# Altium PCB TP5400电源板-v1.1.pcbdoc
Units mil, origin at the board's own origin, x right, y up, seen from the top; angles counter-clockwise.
Board outline 629.92 x 807.09 mil, 2 copper layers (Top Layer, Bottom Layer), stack 62.205 mil thick; 18 components, 11 nets, 48 pads, 36 vias.
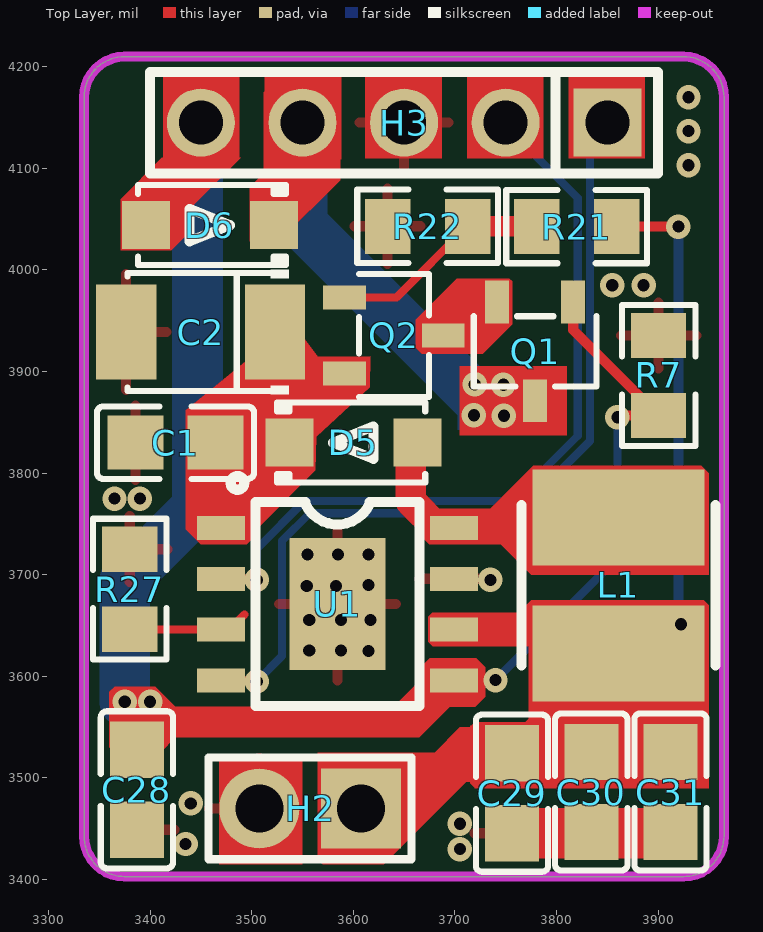
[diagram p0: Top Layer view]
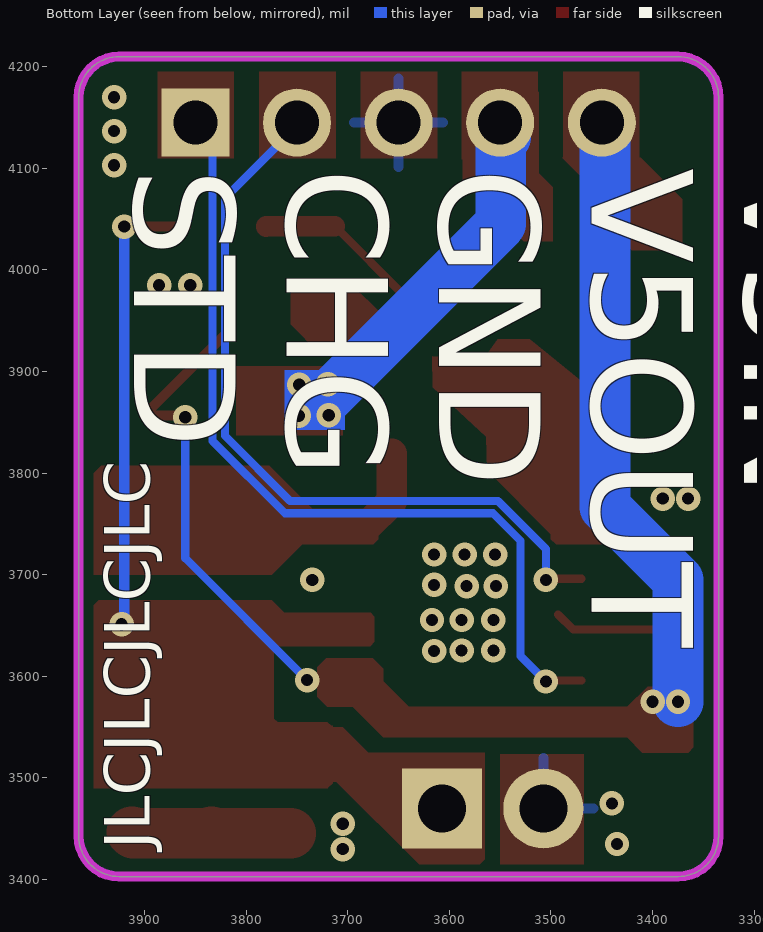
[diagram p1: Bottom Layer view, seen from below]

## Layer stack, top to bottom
Top Solder Mask Layer: solder mask 0.394, Dk 3.3
Top Layer: signal copper 1.378
Dielectric2: surface 59.449, FR4, Dk 4.5
Bottom Layer: signal copper 1.378
Bottom Solder Mask Layer: solder mask 0.394, Dk 3.3

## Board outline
3375,4210 3924.92,4210 cw(c3924.92,4170) 3964.92,4170 3964.92,3442.91 cw(c3924.92,3442.91) 3924.92,3402.91 3375,3402.91 cw(c3375,3442.91) 3335,3442.91 3335,4170 cw(c3375,4170)

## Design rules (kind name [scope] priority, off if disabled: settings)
BoardOutlineClearance copperThickness1oz [All] p0: genericclearance=10 ignorepadtopadclearanceinfootprint=FALSE except(0: Arc-SplitContinuation Track-SplitContinuation SMDPad-SplitContinuation THPad-SplitContinuation Via-SplitContinuation Fill-SplitContinuation Poly-SplitContinuation Region-SplitContinuation Text-SplitContinuation)
BoardOutlineClearance copperThickness2oz [All] p0: genericclearance=10 ignorepadtopadclearanceinfootprint=FALSE except(0: Arc-SplitContinuation Track-SplitContinuation SMDPad-SplitContinuation THPad-SplitContinuation Via-SplitContinuation Fill-SplitContinuation Poly-SplitContinuation Region-SplitContinuation Text-SplitContinuation)
BoardOutlineClearance Plane_innerPlane [All] p0: genericclearance=10 ignorepadtopadclearanceinfootprint=FALSE except(0: Arc-SplitContinuation Track-SplitContinuation SMDPad-SplitContinuation THPad-SplitContinuation Via-SplitContinuation Fill-SplitContinuation Poly-SplitContinuation Region-SplitContinuation Text-SplitContinuation)
BoardOutlineClearance Copper_copperRegion [All] p0: genericclearance=10 ignorepadtopadclearanceinfootprint=FALSE except(0: Arc-SplitContinuation Track-SplitContinuation SMDPad-SplitContinuation THPad-SplitContinuation Via-SplitContinuation Fill-SplitContinuation Poly-SplitContinuation Region-SplitContinuation Text-SplitContinuation)
BoardOutlineClearance otherClearance [All] p0: genericclearance=10 ignorepadtopadclearanceinfootprint=FALSE except(0: Arc-SplitContinuation Track-SplitContinuation SMDPad-SplitContinuation THPad-SplitContinuation Via-SplitContinuation Fill-SplitContinuation Poly-SplitContinuation Region-SplitContinuation Text-SplitContinuation)
Clearance copperThickness1oz [All] p1: gap=7 ignorepadtopadclearanceinfootprint=FALSE
Clearance copperThickness2oz [All] p1: gap=7 ignorepadtopadclearanceinfootprint=FALSE
Clearance Plane_innerPlane [All] p1: gap=7 ignorepadtopadclearanceinfootprint=FALSE
Clearance Copper_copperRegion [All] p1: gap=7 ignorepadtopadclearanceinfootprint=FALSE
Clearance otherClearance [All] p1: gap=7 ignorepadtopadclearanceinfootprint=FALSE
DiffPairsRouting differentialPair [All] p1: maxuncoupledlength=10 minlimit=6 maxlimit=Infinity mostfreqgap=6 toplayer_minwidth=5 toplayer_prefwidth=10 toplayer_maxwidth=100 bottomlayer_minwidth=5 bottomlayer_prefwidth=10 bottomlayer_maxwidth=100
PasteMaskExpansion pasteMaskExpansion [All] p1: expansion=0
PlaneConnect innerPlane [All] p1: planeconnectstyle=Relief reliefexpansion=20 reliefentries=4 reliefconductorwidth=10 reliefairgap=10
PolygonConnect copperRegion [All] p1: connectstyle=Relief reliefentries=4 reliefconductorwidth=10 polygonreliefangle="90 Angle" airgapwidth=10
RoutingVias viaSize [All] p1: viastyle="Through Hole" holewidth=12.0078 minholewidth=11.811 maxholewidth=248.0314 width=12.0078 minwidth=11.811 maxwidth=248.0314
SolderMaskExpansion solderMaskExpansion [All] p1: useseparateexpansions=TRUE expansion=2 expansionbottom=2
Width copperThickness1oz [All] p1: maxlimit=100 minlimit=5 preferedwidth=10
Width copperThickness2oz [All] p1: maxlimit=100 minlimit=8 preferedwidth=10

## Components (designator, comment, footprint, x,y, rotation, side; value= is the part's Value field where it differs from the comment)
C1 "" C0805_1 3425,3830 r0 top
C2 "" CASE-B_3528 3449.7,3938.89 r180 top
C28 "" C0805_1 3387.05,3488.37 r270 top
C29 "" C0805_1 3756.26,3485 r90 top
C30 "" C0805_1 3834.25,3486.18 r90 top
C31 "" C0805_1 3912.26,3486.18 r90 top
D5 "" SOD-123FL_L2.8-W1.8-LS3.7-RD 3600,3830 r0 top
D6 "" SOD-123FL_L2.8-W1.8-LS3.7-RD 3458.78,4044.08 r180 top
H2 "" HDR-TH_2P-P2.54-V-M_1 3557.48,3470 r180 top
H3 "" HDR-TH_5P-P2.54-V-M_1 3650,4145 r180 top
L1 "" IND-SMD_L4.5-W4.0_SCCD43 3861.04,3689.67 r270 top
Q1 "" SOT-23-3_L2.9-W1.6-P1.90-LS2.8-BR_1 3779.04,3920 r90 top
Q2 "" SOT-23-3_L2.9-W1.6-P1.90-LS2.8-BR_1 3640,3935.58 r180 top
R7 "" R0805_1 3900.57,3896.21 r270 top
R21 "" R0805_1 3819.88,4042.7 r180 top
R22 "" R0805_1 3673.23,4042.99 r180 top
R27 "" R0805_1 3380,3685.82 r270 top
U1 "" ESOP-8_L4.9-W3.9-P1.27-LS6.0-BL-EP 3584.43,3671.09 r270 top

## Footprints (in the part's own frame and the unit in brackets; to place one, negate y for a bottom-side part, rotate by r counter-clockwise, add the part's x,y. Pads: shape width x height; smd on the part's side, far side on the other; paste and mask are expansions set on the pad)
C0805_1 [mm]
  rect 1.41x1.35 smd: 1(-1,0) 2(1,0)
  silkscreen extent -1.96,-0.9 1.96,0.9
CASE-B_3528 [mil]
  rect 59.3x93.54 smd: 1(-73.25,0) 2(73.25,0)
  silkscreen extent -87,-61 72,61
ESOP-8_L4.9-W3.9-P1.27-LS6.0-BL-EP [mm]
  rect 0.6x1.2 smd: 1(-1.905,-2.908) 2(-0.635,-2.908) 3(0.635,-2.908) 4(1.905,-2.908) 5(1.905,2.908) 6(0.635,2.908) 7(-0.635,2.908) 8(-1.905,2.908)
  rect 3.3x2.4 smd: 9(0,0)
  silkscreen extent -3.2,-2.67 2.55,2.05
HDR-TH_2P-P2.54-V-M_1 [mm]
  rect 2x2 hole 1.2: 1(-1.27,0)
  round 2 hole 1.2: 2(1.27,0)
  silkscreen extent -2.54,-1.27 2.54,1.27
HDR-TH_5P-P2.54-V-M_1 [mm]
  rect 1.7x1.7 hole 1.1: 1(-5.08,0)
  round 1.7 hole 1.1: 2(-2.54,0) 3(0,0) 4(2.54,0) 5(5.08,0)
  silkscreen extent -6.35,-1.27 6.35,1.27
IND-SMD_L4.5-W4.0_SCCD43 [mm]
  rect 2.4x4.3 smd: 1(-1.7,0) 2(1.7,0)
  silkscreen extent -2,-2.43 2,2.43
R0805_1 [mm]
  rect 1.133x1.377 smd: 1(-1,0) 2(1,0)
  silkscreen extent -1.76,-0.92 1.76,0.92
SOD-123FL_L2.8-W1.8-LS3.7-RD [mm]
  rect 1.2x1.2 smd: 1(-1.6,0) 2(1.6,0)
  silkscreen extent -1.9,-1 1.8,1
SOT-23-3_L2.9-W1.6-P1.90-LS2.8-BR_1 [mm]
  rect 1.07x0.6 smd: 1(1.235,-0.95) 2(1.235,0.95) 3(-1.235,0)
  silkscreen extent -0.88,-1.54 0.88,1.54

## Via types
v1: diameter 24.02, hole 12.01, Top Layer to Bottom Layer, 36 vias

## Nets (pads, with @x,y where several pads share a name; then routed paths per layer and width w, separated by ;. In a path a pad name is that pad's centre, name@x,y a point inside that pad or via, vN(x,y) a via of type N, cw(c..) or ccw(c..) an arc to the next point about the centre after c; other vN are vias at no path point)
$1N374: D5.2 L1.1 U1.8 | length 83.8
  Top Layer w30: D5.2@3656.75,3819.3 3656.75,3772.19 U1.8@3682.7,3746.24
$1N391: R27.2 U1.3 | length 119.4
  Top Layer w8: R27.2 3380.36,3646.09 U1.3 3478.03,3646.09 3493.03,3661.09
$1N4929: Q2.1 R21.2 R22.1 | length 218.3
  Top Layer w8: Q2.1 3642.58,3972.98 R22.1
  Top Layer w20: R22.1 3780.21,4042.99 R21.2
BAT5V: C1.2 C2.1 D5.1 Q2.2 U1.1
BAT5V_OUT: Q1.2 Q2.3
CHRG: H3.2 U1.2 | length 767
  Top Layer w8: U1.2 3503.91,3696.09 v1(3505,3695)
  Bottom Layer w8: v1(3505,3695) 3505,3725.41 3552.17,3772.58 3756.76,3772.58 3820.99,3836.81 3820.99,4070.7 H3.2@3746.69,4145
GND: C1.1 C2.2 C28.2 C29.1 C30.1 C31.1 H2.2 H3.3 R7.1 R22.2 R27.1 U1.7 U1.9 | length 158.2
  Top Layer w50: C29.1 C30.1@3833.07,3445.63 ; C30.1 C30.1@3833.07,3445.63 ; C31.1 3911.08,3445.63 C30.1@3833.07,3445.63
  other v1: 3705,3430 3435,3435 3705,3455 3440,3475 3556.71,3625.5 3588.01,3625.5 3615,3625 3556.71,3655.47 3588.01,3655.47 3617.08,3655.47 3554.24,3688.88 3583.01,3688.88 3615,3690 3735,3695 3555,3720 3585,3720 3615,3720 3365,3775 3390,3775 3855,3985 3885.75,3985 3930,4103.13 3930,4136.67 3930,4170
STDBY: H3.1 U1.4 | length 846.2
  Top Layer w8: U1.4 3503.91,3596.09 v1(3505,3595)
  Bottom Layer w8: v1(3505,3595) 3530,3620 3530,3733.44 3557.14,3760.58 3761.73,3760.58 3832.99,3831.84 3832.99,4132.48 H3.1@3845.36,4144.85
USB5V: C28.1 D6.2 H3.5 Q1.1 R7.2 U1.5 | length 1114.1
  Top Layer w10: U1.5@3722.2,3595.65 3739.32,3595.65 v1(3740,3596.33) ; Q1.1 3816.44,3940.97 R7.2 3861.84,3856.84 v1(3860,3855)
  Bottom Layer w8: v1(3740,3596.33) 3860,3716.33 v1(3860,3855)
  Bottom Layer w50: v1(3375,3575) 3375,3695 3446.69,3766.69 H3.5@3446.69,4145
  other v1: 3400,3575
V5OUT: D6.1 H3.4 Q1.3 | length 329.6
  Bottom Layer w50: H3.4@3544.66,4130.89 3549.45,4126.1 3549.45,4045.45 3720.72,3874.19
  other v1: 3748.27,3856.49 3718.72,3857.02 3719.52,3887.36 3747.73,3887.09
VBAT: C29.2 C30.2 C31.2 H2.1 L1.2 R21.1 U1.6 | length 453.2
  Top Layer w10: R21.1 v1(3920,4042.7)
  Bottom Layer w10: v1(3920,4042.7) 3920,3653.89 v1(3922.61,3651.28)

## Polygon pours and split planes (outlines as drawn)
GND on Top Layer (solid, remove dead copper, pour order 0): 3000,4385 4150,4385 4150,3260 3000,3260
GND on Bottom Layer (solid, remove dead copper, pour order 2): 3185,4295 4490,4295 4490,3215 3185,3215

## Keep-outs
Board Outline Layer:
  the board outline again, w10

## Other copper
Top Layer:
  region net $1N374: 3942.62,3807.38 3950,3800 3950,3700 3775,3700 3745,3730 3675,3730 3670,3735 3670,3758.42 3676.58,3765 3735,3765 3777.38,3807.38
  region net VBAT: 3775,3675 3945,3675 3950,3670 3950,3490 3719.64,3490 3719.64,3490.36 3715,3495 3715,3551.31 3716.31,3551.31 3720,3555 3769.15,3555 3772.64,3558.49 3772.64,3629.7 3678.06,3629.7 3673.79,3633.97 3673.79,3658.79 3677.55,3662.55 3762.55,3662.55
  region net USB5V: 3365,3590 3405,3590 3425,3570 3640,3570 3665,3595 3665,3607.55 3675.18,3617.73 3721.1,3617.73 3730,3608.82 3730,3580 3720,3570 3695,3570 3665,3540 3425,3540 3410,3525 3365,3525 3360,3530 3360,3585
  region net VBAT: 3565,3525 3680,3525 3705,3550 3746.26,3550 3746.26,3504.46 3738.13,3496.33 3711.33,3496.33 3629.85,3414.85 3570.15,3414.85 3565,3420
  region net USB5V: 3411.71,4110.52 3370.91,4069.73 3370.91,4019.35 3420.67,4019.35 3437.04,4035.72 3437.04,4058.49 3489.07,4110.52
  region net BAT5V_OUT: 3753.56,3991.54 3756.35,3988.75 3756.35,3946.43 3727.61,3917.68 3667.32,3917.68 3661.73,3923.27 3661.73,3950.42 3661.34,3950.82 3701.92,3991.41 3726.19,3991.41 3726.32,3991.54
  region net V5OUT: 3705,3905 3810,3905 3810,3837.22 3705,3837.22
  region net V5OUT: 3498.22,4081.22 3512,4095 3512,4175 3527,4190 3572,4190 3587,4175 3587,4088.29 3526.81,4028.1 3498.22,4028.1
  region net BAT5V: 3495,3730 3500,3735 3500,3740 3562.71,3802.71 3563.51,3836.01 3616.43,3884.37 3616.83,3914.92 3564.92,3914.67 3552.39,3931.96 3520.81,3931.96 3435,3862.15 3435,3745 3450,3730
  region net USB5V: 3413,4195 3488,4195 3488,4110 3413,4110
  region net V5OUT: 3513,4195 3588,4195 3588,4108.87 3513,4108.87
  region net GND: 3612,4195 3687,4195 3687,4110 3612,4110
  region net CHRG: 3712,4195 3787,4195 3787,4110 3712,4110
  region net STDBY: 3812,4195 3887,4195 3887,4110 3812,4110
  region net GND: 3467.89,3523.37 3550,3523.37 3550,3415 3467.89,3415
Bottom Layer:
  region net V5OUT: 3702.96,3901.12 3761.82,3901.12 3761.82,3842.71 3702.96,3842.71

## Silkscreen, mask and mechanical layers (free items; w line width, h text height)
Bottom Silkscreen Layer:
  text "V5IN / V5OUT / GND / CHG / STD" at 3910,4100 h100 r90
  text "JLCJLCJLCJLC" at 3895,3430 h45 r270

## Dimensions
3335,3220 to 3965,3220 on Document Layer
4194.96,3398.21 to 4199.96,4208.21 on Document Layer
